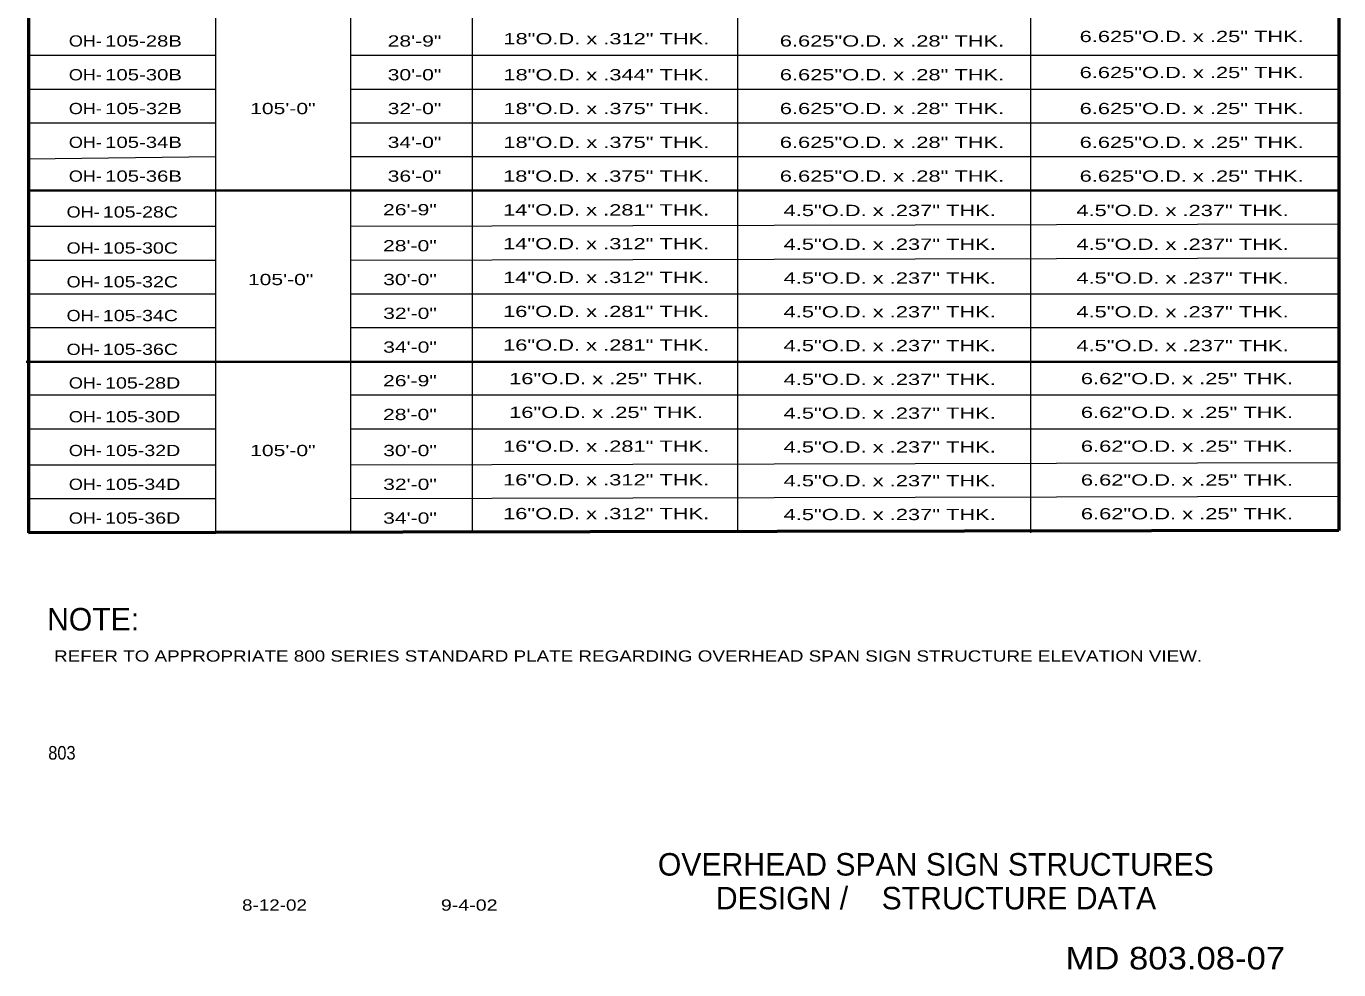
# Model space of a CAD drawing. Extents: x -34822.8 to -34815.8, y -181502.4 to -181492.3.
# Drawn here: x -34822.77 to -34815.78, y -181502.37 to -181497.35 of the extents above; entities that cross this region are included whole.
import ezdxf
from ezdxf.enums import TextEntityAlignment as Align

# ---------------------------------------------------------------- set-up
doc = ezdxf.new("R2010")
doc.units = 0
doc.header["$LTSCALE"] = 0.024
doc.layers.add('1', color=7, linetype='Continuous', lineweight=13)
doc.layers.add('12', color=7, linetype='Continuous')
doc.layers.add('13', color=7, linetype='Continuous')

msp = doc.modelspace()

# ---------------------------------------------------------------- linework, layer by layer
at = {"layer": '1', "lineweight": 53}
for p, q in [((-34822.756, -181492.336), (-34822.756, -181500.045)), ((-34815.779, -181492.336), (-34815.779, -181500.033)), ((-34815.779, -181500.033), (-34822.756, -181500.045))]:
    msp.add_line(p, q, dxfattribs=at)
at = {"layer": '1'}
for p, q in [((-34821.761, -181492.336), (-34821.761, -181500.045)), ((-34821.042, -181492.336), (-34821.042, -181500.045)), ((-34820.394, -181492.336), (-34820.394, -181500.045)), ((-34818.98, -181492.336), (-34818.98, -181500.045)), ((-34817.421, -181492.336), (-34817.421, -181500.045)), ((-34821.761, -181497.503), (-34822.756, -181497.503)), ((-34815.779, -181497.503), (-34821.042, -181497.503)), ((-34821.761, -181497.683), (-34822.756, -181497.683)), ((-34815.779, -181497.683), (-34821.042, -181497.683)), ((-34821.761, -181497.863), (-34822.756, -181497.863)), ((-34815.779, -181497.863), (-34821.042, -181497.863)), ((-34821.761, -181498.043), (-34822.756, -181498.055)), ((-34815.779, -181498.043), (-34821.042, -181498.043)), ((-34821.761, -181498.414), (-34822.756, -181498.414)), ((-34815.779, -181498.402), (-34821.042, -181498.414)), ((-34821.761, -181498.594), (-34822.756, -181498.594)), ((-34815.779, -181498.582), (-34821.042, -181498.594)), ((-34821.761, -181498.774), (-34822.756, -181498.774)), ((-34815.779, -181498.774), (-34821.042, -181498.774)), ((-34821.761, -181498.954), (-34822.756, -181498.954)), ((-34815.779, -181498.954), (-34821.042, -181498.954)), ((-34821.761, -181499.313), (-34822.756, -181499.313)), ((-34815.779, -181499.313), (-34821.042, -181499.313)), ((-34821.761, -181499.493), (-34822.756, -181499.493)), ((-34815.779, -181499.493), (-34821.042, -181499.493)), ((-34821.761, -181499.685), (-34822.756, -181499.685)), ((-34815.779, -181499.673), (-34821.042, -181499.685)), ((-34815.779, -181499.853), (-34821.042, -181499.865)), ((-34821.761, -181499.865), (-34822.756, -181499.865))]:
    msp.add_line(p, q, dxfattribs=at)
at = {"layer": '1', "lineweight": 35}
for p, q in [((-34815.779, -181498.222), (-34822.756, -181498.222)), ((-34815.779, -181499.134), (-34822.768, -181499.134))]:
    msp.add_line(p, q, dxfattribs=at)

# ---------------------------------------------------------------- texts
at = {"layer": '12'}
msp.add_text('NOTE:', height=0.12, dxfattribs=at).set_placement((-34822.412, -181500.566), align=Align.CENTER)
at = {"layer": '13'}
for s, height, width, p in [('OH-', 0.05992, 1.2, (-34822.453, -181497.455)), ('28\'-9"', 0.05992, 1.4, (-34820.7005, -181497.455)), ('18"O.D. x .312" THK.', 0.05992, 1.45, (-34819.679, -181497.443)), ('6.625"O.D. x .28" THK.', 0.06, 1.45, (-34818.158, -181497.455)), ('6.625"O.D. x .25" THK.', 0.05992, 1.45, (-34816.562, -181497.431)), ('OH-', 0.05992, 1.2, (-34822.453, -181497.635)), ('30\'-0"', 0.05992, 1.4, (-34820.7005, -181497.635)), ('18"O.D. x .344" THK.', 0.05992, 1.45, (-34819.679, -181497.635)), ('6.625"O.D. x .28" THK.', 0.06, 1.45, (-34818.158, -181497.635)), ('6.625"O.D. x .25" THK.', 0.05992, 1.45, (-34816.562, -181497.623)), ('OH-', 0.05992, 1.2, (-34822.453, -181497.815)), ('105\'-0"', 0.05992, 1.4, (-34821.4015, -181497.815)), ('32\'-0"', 0.05992, 1.4, (-34820.7005, -181497.815)), ('18"O.D. x .375" THK.', 0.05992, 1.45, (-34819.679, -181497.815)), ('6.625"O.D. x .28" THK.', 0.06, 1.45, (-34818.158, -181497.815)), ('6.625"O.D. x .25" THK.', 0.05992, 1.45, (-34816.562, -181497.815)), ('OH-', 0.05992, 1.2, (-34822.453, -181497.995)), ('34\'-0"', 0.05992, 1.4, (-34820.7005, -181497.995)), ('18"O.D. x .375" THK.', 0.05992, 1.45, (-34819.679, -181497.995)), ('6.625"O.D. x .28" THK.', 0.06, 1.45, (-34818.158, -181497.995)), ('6.625"O.D. x .25" THK.', 0.05992, 1.45, (-34816.562, -181497.995)), ('OH-', 0.05992, 1.2, (-34822.453, -181498.175)), ('36\'-0"', 0.05992, 1.4, (-34820.7005, -181498.175)), ('18"O.D. x .375" THK.', 0.06, 1.45, (-34819.68, -181498.175)), ('6.625"O.D. x .28" THK.', 0.06, 1.45, (-34818.158, -181498.175)), ('6.625"O.D. x .25" THK.', 0.05992, 1.45, (-34816.562, -181498.175)), ('OH-', 0.05992, 1.2, (-34822.465, -181498.366)), ('26\'-9"', 0.06, 1.4, (-34820.725, -181498.354)), ('14"O.D. x .281" THK.', 0.06, 1.45, (-34819.68, -181498.355)), ('4.5"O.D. x .237" THK.', 0.06, 1.45, (-34818.17, -181498.358)), ('4.5"O.D. x .237" THK.', 0.06, 1.45, (-34816.611, -181498.358)), ('OH-', 0.05992, 1.2, (-34822.465, -181498.558)), ('28\'-0"', 0.06, 1.4, (-34820.725, -181498.546)), ('14"O.D. x .312" THK.', 0.06, 1.45, (-34819.68, -181498.535)), ('4.5"O.D. x .237" THK.', 0.06, 1.45, (-34818.17, -181498.538)), ('4.5"O.D. x .237" THK.', 0.06, 1.45, (-34816.611, -181498.538)), ('105\'-0"', 0.05992, 1.4, (-34821.4135, -181498.726)), ('30\'-0"', 0.05992, 1.4, (-34820.7245, -181498.726)), ('14"O.D. x .312" THK.', 0.06, 1.45, (-34819.68, -181498.715)), ('4.5"O.D. x .237" THK.', 0.06, 1.45, (-34818.17, -181498.718)), ('4.5"O.D. x .237" THK.', 0.06, 1.45, (-34816.611, -181498.718)), ('OH-', 0.05992, 1.2, (-34822.465, -181498.738)), ('OH-', 0.05992, 1.2, (-34822.465, -181498.918)), ('32\'-0"', 0.05992, 1.4, (-34820.7245, -181498.906)), ('16"O.D. x .281" THK.', 0.06, 1.45, (-34819.68, -181498.896)), ('4.5"O.D. x .237" THK.', 0.06, 1.45, (-34818.17, -181498.898)), ('4.5"O.D. x .237" THK.', 0.06, 1.45, (-34816.611, -181498.898)), ('16"O.D. x .281" THK.', 0.06, 1.45, (-34819.68, -181499.075)), ('4.5"O.D. x .237" THK.', 0.06, 1.45, (-34818.17, -181499.078)), ('4.5"O.D. x .237" THK.', 0.06, 1.45, (-34816.611, -181499.078)), ('OH-', 0.05992, 1.2, (-34822.465, -181499.098)), ('34\'-0"', 0.05992, 1.4, (-34820.7245, -181499.086)), ('OH-', 0.05992, 1.2, (-34822.453, -181499.277)), ('26\'-9"', 0.06, 1.4, (-34820.725, -181499.265)), ('16"O.D. x .25" THK.', 0.06, 1.45, (-34819.68, -181499.254)), ('4.5"O.D. x .237" THK.', 0.06, 1.45, (-34818.17, -181499.258)), ('6.62"O.D. x .25" THK.', 0.06, 1.45, (-34816.587, -181499.254)), ('OH-', 0.05992, 1.2, (-34822.453, -181499.457)), ('28\'-0"', 0.06, 1.4, (-34820.725, -181499.445)), ('16"O.D. x .25" THK.', 0.06, 1.45, (-34819.68, -181499.434)), ('4.5"O.D. x .237" THK.', 0.06, 1.45, (-34818.17, -181499.438)), ('6.62"O.D. x .25" THK.', 0.06, 1.45, (-34816.587, -181499.434)), ('OH-', 0.05992, 1.2, (-34822.453, -181499.637)), ('105\'-0"', 0.05992, 1.4, (-34821.4015, -181499.637)), ('30\'-0"', 0.05992, 1.4, (-34820.7245, -181499.637)), ('16"O.D. x .281" THK.', 0.06, 1.45, (-34819.68, -181499.614)), ('4.5"O.D. x .237" THK.', 0.06, 1.45, (-34818.17, -181499.618)), ('6.62"O.D. x .25" THK.', 0.06, 1.45, (-34816.587, -181499.614)), ('OH-', 0.05992, 1.2, (-34822.453, -181499.817)), ('32\'-0"', 0.05992, 1.4, (-34820.7245, -181499.817)), ('16"O.D. x .312" THK.', 0.06, 1.45, (-34819.68, -181499.793)), ('4.5"O.D. x .237" THK.', 0.06, 1.45, (-34818.17, -181499.798)), ('6.62"O.D. x .25" THK.', 0.06, 1.45, (-34816.587, -181499.794)), ('16"O.D. x .312" THK.', 0.06, 1.45, (-34819.68, -181499.973)), ('4.5"O.D. x .237" THK.', 0.06, 1.45, (-34818.17, -181499.978)), ('6.62"O.D. x .25" THK.', 0.06, 1.45, (-34816.587, -181499.974)), ('OH-', 0.05992, 1.2, (-34822.453, -181499.997)), ('34\'-0"', 0.05992, 1.4, (-34820.7245, -181499.997)), ('REFER TO APPROPRIATE 800 SERIES STANDARD PLATE REGARDING OVERHEAD SPAN SIGN STRUCTURE ELEVATION VIEW.', 0.06, 1.25, (-34819.563, -181500.732)), ('803', 0.07251, 0.9, (-34822.578, -181501.254))]:
    msp.add_text(s, height=height, dxfattribs=dict(at, width=width)).set_placement(p, align=Align.CENTER)
for s, height, width, p in [('105-28B', 0.05992, 1.35, (-34822.348, -181497.455)), ('105-30B', 0.05992, 1.35, (-34822.348, -181497.635)), ('105-32B', 0.05992, 1.35, (-34822.348, -181497.815)), ('105-34B', 0.05992, 1.35, (-34822.348, -181497.995)), ('105-36B', 0.05992, 1.35, (-34822.348, -181498.175)), ('105-28C', 0.06, 1.3, (-34822.36, -181498.366)), ('105-30C', 0.06, 1.3, (-34822.36, -181498.558)), ('105-32C', 0.06, 1.3, (-34822.36, -181498.738)), ('105-34C', 0.06, 1.3, (-34822.36, -181498.918)), ('105-36C', 0.06, 1.3, (-34822.36, -181499.098)), ('105-28D', 0.06, 1.3, (-34822.348, -181499.277)), ('105-30D', 0.06, 1.3, (-34822.348, -181499.457)), ('105-32D', 0.06, 1.3, (-34822.348, -181499.637)), ('105-34D', 0.06, 1.3, (-34822.348, -181499.817)), ('105-36D', 0.06, 1.3, (-34822.348, -181499.997)), ('8-12-02', 0.06, 1.25, (-34821.619, -181502.059)), ('9-4-02', 0.06, 1.3, (-34820.56, -181502.059)), ('MD 803.08-07', 0.12, 1.15, (-34817.234, -181502.372))]:
    msp.add_text(s, height=height, dxfattribs=dict(at, width=width)).set_placement(p)
for s, p in [('OVERHEAD SPAN SIGN STRUCTURES', (-34817.9245, -181501.872)), ('DESIGN /    STRUCTURE DATA', (-34817.9235, -181502.052))]:
    msp.add_text(s, height=0.12, dxfattribs=at).set_placement(p, align=Align.CENTER)

doc.saveas('drawing.dxf')
